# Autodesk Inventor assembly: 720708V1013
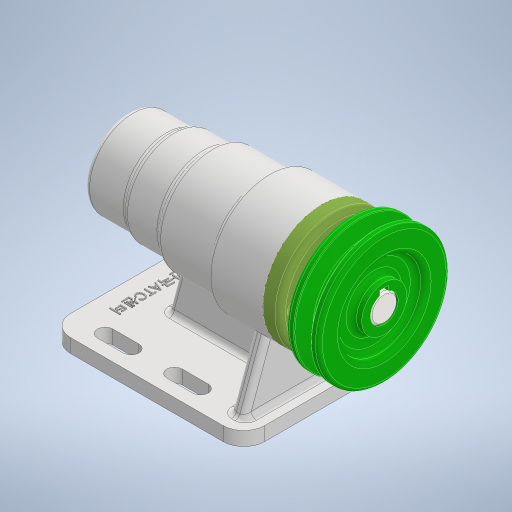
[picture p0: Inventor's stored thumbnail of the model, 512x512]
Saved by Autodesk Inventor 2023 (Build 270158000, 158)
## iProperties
Created: 2022-07
Part Number: 720708V1013
Document SubType Name: Assembly
Designer: owner
Author: owner
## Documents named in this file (12)
- C:\Users\owner\Desktop\720708V1013\720708V1013.iam
- C:\Users\owner\Desktop\720708V1013\본체.ipt
- C:\Users\owner\Desktop\720708V1013\V벨트풀리.ipt
- C:\Users\owner\Desktop\720708V1013\멈춤나사 M3.ipt
- C:\Users\owner\Desktop\720708V1013\베어링 6004.ipt
- C:\Users\owner\Desktop\720708V1013\베어링 51202.ipt
- C:\Users\owner\Desktop\720708V1013\볼트 M4.ipt
- C:\Users\owner\Desktop\720708V1013\어댑터슬리브.ipt
- C:\Users\owner\Desktop\720708V1013\오일 실 20x35x7.ipt
- C:\Users\owner\Desktop\720708V1013\축.ipt
- C:\Users\owner\Desktop\720708V1013\커버.ipt
- C:\Users\owner\Desktop\720708V1013\키 5x5.ipt
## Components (1 placed, 1 different names)
1. V벨트풀리:1
